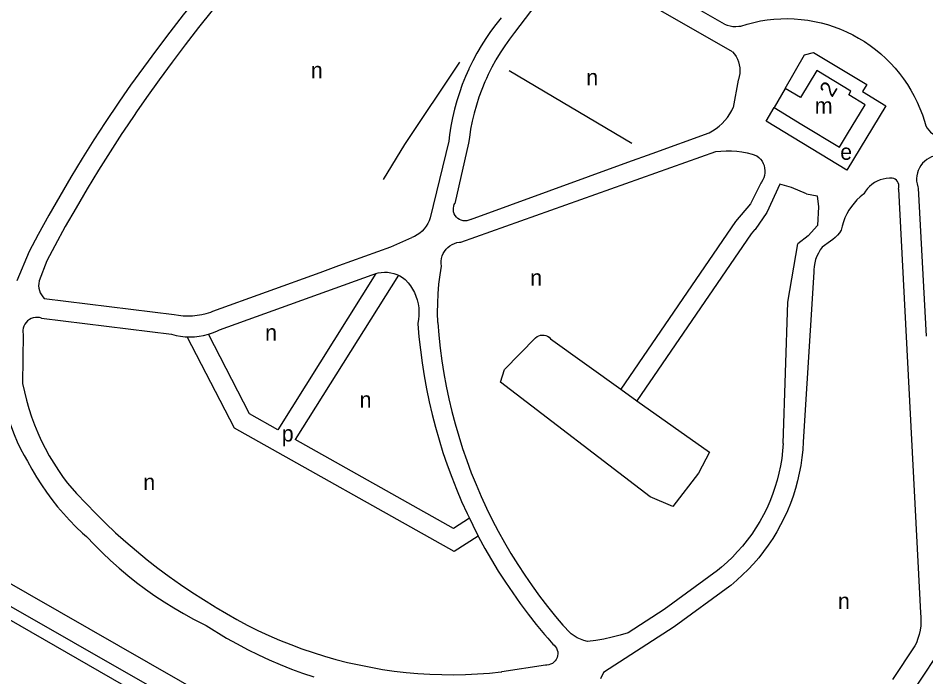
# Model space of a CAD drawing. Extents: x 157155 to 159285, y 385001 to 386651.
# Drawn here: x 158780.5 to 159008.3, y 385150.6 to 385315.8 of the extents above; entities that cross this region are included whole.
import ezdxf

# ---------------------------------------------------------------- set-up
doc = ezdxf.new("R2010")
doc.units = 0
for name, color, linetype in [('BLT_Basislijn', 7, 'Continuous'), ('BLT_Bebouwing', 7, 'Continuous'), ('BLT_Centroide', 7, 'Continuous'), ('BLT_Huisnummer', 7, 'Continuous')]:
    doc.layers.add(name, color=color, linetype=linetype)

msp = doc.modelspace()

# ---------------------------------------------------------------- linework, layer by layer
at = {"layer": 'BLT_Basislijn'}
for p, q in [((158957.77, 385314.36), (158928.1, 385331.36)), ((158917.02, 385328.1), (158905.11, 385312.23)), ((158959.82, 385307.43), (158921.7, 385329.26)), ((158523.9, 385310.24), (158946.21, 385068.98)), ((158903.73, 385302.73), (158934.55, 385284.5)), ((158961.21, 385300.27), (158959.97, 385293.43)), ((158939.64, 385281.89), (158953.93, 385287.09)), ((158888.59, 385285), (158883.93, 385265.77)), ((158893.56, 385284.46), (158890.09, 385269.37)), ((158891.6, 385259.68), (158955.6, 385282.37)), ((158933.5, 385279.72), (158939.64, 385281.89)), ((158894.04, 385265.33), (158933.5, 385279.72)), ((158966.88, 385274.47), (158964.36, 385269.26)), ((159001.44, 385272.94), (159007.03, 385166.63)), ((159006.43, 385273.2), (159008.38, 385236.11)), ((158874.07, 385258.48), (158879.27, 385260.79)), ((158984.41, 385259.91), (158982.32, 385258.42)), ((158783.22, 385257.3), (158780.15, 385249.92)), ((158860.99, 385253.76), (158874.07, 385258.48)), ((158787.65, 385254.97), (158785.75, 385249.92)), ((158856.3, 385252.06), (158860.99, 385253.76)), ((158829.33, 385242.32), (158856.3, 385252.06)), ((158831.02, 385237.62), (158869.33, 385251.46)), ((158870.3, 385251.8), (158845.69, 385212.61)), ((158875.93, 385251.36), (158850.05, 385210.15)), ((158980.24, 385252.09), (158977.56, 385209.54)), ((158786.99, 385245.56), (158819.61, 385241.52)), ((158662.43, 385240.32), (158951.28, 385075.3)), ((158786.37, 385240.59), (158818.99, 385236.55)), ((158781.71, 385236.55), (158781.59, 385224.19)), ((158914.15, 385235.44), (158931.77, 385222.79)), ((158931.77, 385222.79), (158935.82, 385219.86)), ((158917.2, 385163.58), (158919.04, 385161.63)), ((158913.42, 385160.31), (158914.68, 385158.83)), ((159005.6, 385158.37), (159000, 385149.93)), ((159010.88, 385155.73), (158959.48, 385078.25)), ((158912.82, 385153.55), (158901.91, 385151.87))]:
    msp.add_line(p, q, dxfattribs=at)
for points in [[(158828.89, 385325.2), (158825.37, 385320.96), (158821.91, 385316.67), (158818.52, 385312.33), (158815.18, 385307.94), (158811.92, 385303.5), (158808.71, 385299.02), (158807.03, 385296.58)], [(158832.71, 385321.98), (158829.21, 385317.77), (158825.78, 385313.5), (158822.41, 385309.19), (158819.1, 385304.83), (158815.86, 385300.42), (158812.68, 385295.97), (158810.18, 385292.34)], [(158522.97, 385314.23), (158948.8, 385070.96), (158946.21, 385068.98)], [(158901.7, 385315.97), (158900.35, 385314.27), (158899.07, 385312.53), (158897.85, 385310.74), (158896.69, 385308.91), (158895.87, 385307.5)], [(158957.77, 385314.36), (158958.46, 385314.09), (158959.18, 385313.9), (158959.92, 385313.79), (158960.66, 385313.76), (158961.4, 385313.81), (158961.88, 385313.88)], [(158961.88, 385313.88), (158963.51, 385314.38), (158965.16, 385314.8), (158966.83, 385315.15), (158968.51, 385315.42), (158970.2, 385315.6), (158971.9, 385315.71), (158973.6, 385315.73), (158975.3, 385315.68), (158977, 385315.55), (158978.69, 385315.33), (158980.37, 385315.04), (158982.03, 385314.67), (158983.67, 385314.22), (158985.29, 385313.7), (158986.88, 385313.1), (158988.45, 385312.42), (158989.98, 385311.68), (158991.47, 385310.86), (158992.92, 385309.97), (158994.33, 385309.02), (158995.7, 385308), (158997.01, 385306.91), (158998.27, 385305.77), (158999.48, 385304.57), (159000.63, 385303.31), (159001.71, 385302), (159002.74, 385300.64), (159003.7, 385299.24), (159004.6, 385297.79), (159005.42, 385296.3), (159006.17, 385294.77), (159006.85, 385293.21), (159007.46, 385291.62), (159007.99, 385290.01), (159008.3, 385288.81)], [(158905.11, 385312.23), (158903.84, 385310.59), (158902.63, 385308.91), (158901.5, 385307.18), (158900.43, 385305.41), (158900.31, 385305.19)], [(158895.87, 385307.5), (158895.6, 385307.04), (158894.59, 385305.13), (158893.64, 385303.18), (158893.59, 385303.05)], [(158959.82, 385307.43), (158960.29, 385306.86), (158960.7, 385306.24), (158961.04, 385305.57), (158961.31, 385304.88), (158961.51, 385304.16), (158961.62, 385303.42), (158961.66, 385302.68), (158961.61, 385301.93), (158961.49, 385301.2), (158961.29, 385300.48), (158961.21, 385300.27)], [(158973.05, 385298.22), (158977.91, 385306.62), (158980.13, 385307.25), (158993.5, 385299.22), (158992.43, 385297.45), (158998.32, 385293.88), (158988.52, 385277.69), (158968.22, 385289.99), (158970.25, 385293.44)], [(158872.21, 385275.35), (158877.55, 385284.12), (158891.34, 385304.78)], [(158900.31, 385305.19), (158899.42, 385303.59), (158898.49, 385301.74), (158898.03, 385300.73)], [(158893.59, 385303.05), (158892.77, 385301.2), (158891.97, 385299.18), (158891.25, 385297.14), (158890.6, 385295.08), (158890.03, 385292.99), (158889.54, 385290.88), (158889.12, 385288.75), (158888.79, 385286.61), (158888.59, 385285)], [(158898.03, 385300.73), (158897.64, 385299.86), (158896.85, 385297.94), (158896.14, 385296), (158895.51, 385294.03), (158894.95, 385292.03), (158894.47, 385290.02), (158894.07, 385287.98), (158893.74, 385285.94), (158893.56, 385284.46)], [(158807.03, 385296.58), (158805.58, 385294.49), (158802.51, 385289.92), (158802.36, 385289.68)], [(158953.93, 385287.09), (158954.82, 385287.58), (158955.67, 385288.13), (158956.47, 385288.76), (158957.22, 385289.44), (158957.91, 385290.18), (158958.55, 385290.97), (158959.12, 385291.81), (158959.62, 385292.7), (158959.97, 385293.43)], [(158810.18, 385292.34), (158809.57, 385291.47), (158806.92, 385287.52)], [(158802.36, 385289.68), (158799.51, 385285.3), (158796.57, 385280.64), (158793.7, 385275.93), (158790.9, 385271.19), (158788.17, 385266.4), (158785.51, 385261.58), (158783.22, 385257.3)], [(159008.3, 385288.81), (159008.65, 385288.24), (159009.06, 385287.73), (159009.53, 385287.26), (159010.06, 385286.86), (159010.62, 385286.52), (159011.23, 385286.25), (159011.86, 385286.06), (159012.52, 385285.94), (159012.83, 385285.92)], [(158806.92, 385287.52), (158806.52, 385286.92), (158803.54, 385282.33), (158800.63, 385277.7), (158797.78, 385273.02), (158795.01, 385268.3), (158792.3, 385263.55), (158789.66, 385258.75), (158787.65, 385254.97)], [(158955.6, 385282.37), (158956.91, 385282.52), (158958.23, 385282.58), (158959.55, 385282.56), (158960.87, 385282.47), (158962.18, 385282.29), (158963.47, 385282.03), (158964.75, 385281.7), (158965.95, 385281.31)], [(158965.95, 385281.31), (158966.43, 385280.92), (158966.85, 385280.47), (158967.21, 385279.97), (158967.5, 385279.43), (158967.72, 385278.86), (158967.87, 385278.26), (158967.93, 385277.64), (158967.92, 385277.03), (158967.82, 385276.42), (158967.65, 385275.83), (158967.4, 385275.27), (158967.08, 385274.74), (158966.88, 385274.47)], [(159013.18, 385281.39), (159012.49, 385281.48), (159011.79, 385281.49), (159011.1, 385281.42), (159010.42, 385281.27), (159009.76, 385281.04), (159009.14, 385280.74), (159008.55, 385280.37), (159008, 385279.93), (159007.52, 385279.44), (159007.09, 385278.89), (159006.72, 385278.3), (159006.43, 385277.67), (159006.21, 385277.01), (159006.07, 385276.32), (159006.01, 385275.63), (159006.02, 385274.93), (159006.12, 385274.25), (159006.3, 385273.57), (159006.43, 385273.2)], [(158999.2, 385275.72), (158998.41, 385275.65), (158997.64, 385275.5), (158996.89, 385275.28), (158996.16, 385274.98), (158995.47, 385274.6), (158994.81, 385274.16), (158994.21, 385273.66), (158993.66, 385273.1), (158993.17, 385272.48), (158992.75, 385271.82), (158992.67, 385271.67)], [(159001.44, 385272.94), (159001.55, 385273.33), (159001.59, 385273.73), (159001.55, 385274.13), (159001.43, 385274.51), (159001.24, 385274.86), (159000.98, 385275.17), (159000.67, 385275.42), (159000.31, 385275.61), (158999.92, 385275.72), (158999.52, 385275.75), (158999.2, 385275.72)], [(158978.36, 385271.81), (158974.59, 385273.36), (158971.7, 385274.24), (158968.44, 385267.06), (158965.52, 385262.81), (158965.35, 385262.73)], [(158978.36, 385271.81), (158981.09, 385271.29), (158981.42, 385268.52), (158981.1, 385263.85), (158978.83, 385261.27), (158976.2, 385259.24)], [(158992.67, 385271.67), (158991.83, 385270.99), (158991.04, 385270.24), (158990.31, 385269.43), (158989.64, 385268.58), (158989.03, 385267.67), (158988.49, 385266.73), (158988.03, 385265.75), (158987.63, 385264.73), (158987.31, 385263.69), (158987.08, 385262.66)], [(158894.04, 385265.33), (158893.6, 385265.14), (158893.12, 385265.02), (158892.64, 385264.99), (158892.15, 385265.03), (158891.69, 385265.16), (158891.24, 385265.36), (158890.84, 385265.62), (158890.48, 385265.96), (158890.19, 385266.34), (158889.96, 385266.77), (158889.8, 385267.23), (158889.73, 385267.71), (158889.73, 385268.19), (158889.81, 385268.67), (158889.97, 385269.13), (158890.09, 385269.37)], [(158964.36, 385269.26), (158960.55, 385264.8), (158931.77, 385222.79)], [(158883.93, 385265.77), (158883.65, 385265.03), (158883.31, 385264.32), (158882.9, 385263.65), (158882.42, 385263.02), (158881.88, 385262.45), (158881.28, 385261.93), (158880.63, 385261.48), (158879.95, 385261.09), (158879.27, 385260.79)], [(158965.35, 385262.73), (158964.52, 385261.76), (158935.82, 385219.86)], [(158987.08, 385262.66), (158986.65, 385261.99), (158986.15, 385261.38), (158985.59, 385260.81), (158984.98, 385260.3), (158984.41, 385259.91)], [(158886.72, 385253.64), (158886.66, 385254.29), (158886.68, 385254.93), (158886.77, 385255.57), (158886.95, 385256.19), (158887.2, 385256.79), (158887.52, 385257.35), (158887.9, 385257.86), (158888.35, 385258.33), (158888.86, 385258.73), (158889.41, 385259.07), (158889.99, 385259.34), (158890.61, 385259.53), (158891.24, 385259.65), (158891.6, 385259.68)], [(158972.54, 385209.14), (158973.72, 385244.63), (158976.2, 385259.24)], [(158982.32, 385258.42), (158981.81, 385257.7), (158981.36, 385256.93), (158980.99, 385256.13), (158980.68, 385255.3), (158980.46, 385254.44), (158980.31, 385253.56), (158980.24, 385252.68), (158980.24, 385252.09)], [(158885.8, 385239.52), (158885.76, 385241.92), (158885.8, 385244.31), (158885.92, 385246.7), (158886.12, 385249.08), (158886.4, 385251.46), (158886.72, 385253.64)], [(158869.33, 385251.46), (158870.07, 385251.74), (158870.3, 385251.8)], [(158870.3, 385251.8), (158870.84, 385251.95), (158871.63, 385252.08), (158872.43, 385252.13), (158873.22, 385252.1), (158874.01, 385251.99), (158874.79, 385251.81), (158875.54, 385251.55), (158875.93, 385251.36)], [(158875.93, 385251.36), (158876.27, 385251.21), (158876.95, 385250.8), (158877.59, 385250.33), (158877.71, 385250.23)], [(158877.71, 385250.23), (158878.37, 385249.49), (158878.96, 385248.7), (158879.48, 385247.87), (158879.94, 385246.99), (158880.32, 385246.09), (158880.63, 385245.15), (158880.87, 385244.2), (158881.02, 385243.22), (158881.1, 385242.24), (158881.09, 385241.26), (158881.01, 385240.28), (158880.84, 385239.3), (158880.81, 385239.17)], [(158785.75, 385249.92), (158785.64, 385249.32), (158785.62, 385248.71), (158785.67, 385248.11), (158785.81, 385247.52), (158786.02, 385246.95), (158786.3, 385246.42), (158786.65, 385245.92), (158786.99, 385245.56)], [(158819.61, 385241.52), (158820.76, 385241.31), (158821.92, 385241.19), (158823.08, 385241.15), (158824.25, 385241.18), (158825.41, 385241.3), (158826.56, 385241.5), (158827.69, 385241.77), (158828.81, 385242.12), (158829.33, 385242.32)], [(158786.37, 385240.59), (158785.85, 385240.73), (158785.32, 385240.78), (158784.79, 385240.76), (158784.26, 385240.65), (158783.76, 385240.47), (158783.29, 385240.22), (158782.86, 385239.89), (158782.49, 385239.51), (158782.18, 385239.08), (158781.93, 385238.6), (158781.76, 385238.1), (158781.67, 385237.57), (158781.65, 385237.04), (158781.71, 385236.55)], [(158880.81, 385239.17), (158881.09, 385235.88), (158881.44, 385232.61), (158881.88, 385229.35), (158882.39, 385226.09), (158882.99, 385222.86), (158883.66, 385219.63), (158884.41, 385216.43), (158885.24, 385213.24), (158886.14, 385210.07), (158887.12, 385206.93), (158888.18, 385203.81), (158889.31, 385200.72), (158890.52, 385197.66), (158891.8, 385194.62), (158893.16, 385191.62), (158893.74, 385190.4)], [(158885.8, 385239.52), (158886.07, 385236.3), (158886.42, 385233.09), (158886.85, 385229.89), (158887.36, 385226.7), (158887.95, 385223.52), (158888.62, 385220.36), (158889.36, 385217.21), (158890.19, 385214.09), (158891.09, 385210.99), (158892.06, 385207.91), (158893.12, 385204.85), (158894.24, 385201.82), (158895.45, 385198.82), (158896.72, 385195.85), (158898.07, 385192.92), (158899.49, 385190.01), (158900.99, 385187.15), (158902.55, 385184.32), (158904.18, 385181.53), (158905.89, 385178.78), (158907.65, 385176.08), (158909.49, 385173.42), (158911.39, 385170.81), (158913.36, 385168.24), (158915.38, 385165.73), (158917.2, 385163.58)], [(158818.99, 385236.55), (158820.12, 385236.27), (158821.26, 385236.07), (158822.41, 385235.94), (158822.93, 385235.92)], [(158822.93, 385235.92), (158823.57, 385235.9), (158824.72, 385235.93), (158825.88, 385236.05), (158827.02, 385236.24), (158828.24, 385236.55)], [(158828.24, 385236.55), (158829.25, 385236.87), (158830.33, 385237.29), (158831.02, 385237.62)], [(158845.69, 385212.61), (158838.58, 385216.6), (158828.24, 385236.55)], [(158910.38, 385235.67), (158910.75, 385235.95), (158911.15, 385236.16), (158911.59, 385236.29), (158912.05, 385236.35), (158912.5, 385236.33), (158912.95, 385236.23), (158913.38, 385236.06), (158913.76, 385235.81), (158914.15, 385235.44)], [(158895.99, 385185.9), (158889.91, 385182.03), (158834.82, 385212.97), (158822.93, 385235.92)], [(158935.82, 385219.86), (158953.99, 385206.97), (158951.23, 385201.72), (158944.81, 385193.32), (158939.11, 385195.79), (158901.59, 385224.53), (158902.56, 385227.68), (158910.38, 385235.67)], [(158781.59, 385224.19), (158782.03, 385222.08), (158782.55, 385219.98), (158783.15, 385217.91), (158783.82, 385215.86), (158784.57, 385213.83), (158785.39, 385211.83), (158786.28, 385209.87), (158787.25, 385207.94), (158788.29, 385206.05), (158789.4, 385204.19), (158790.57, 385202.38), (158791.81, 385200.61), (158792.87, 385199.22)], [(158776.73, 385220.7), (158777.12, 385218.79), (158777.59, 385216.9), (158778.14, 385215.04), (158778.77, 385213.2), (158779.46, 385211.38), (158780.24, 385209.59), (158781.09, 385207.84), (158782, 385206.13), (158782.85, 385204.68)], [(158893.74, 385190.4), (158889.75, 385187.86), (158850.05, 385210.15)], [(158972.54, 385209.14), (158972.39, 385207.27), (158972.16, 385205.41), (158971.85, 385203.56), (158971.47, 385201.73), (158971, 385199.91), (158970.46, 385198.11), (158969.85, 385196.34), (158969.15, 385194.6), (158968.39, 385192.88), (158967.55, 385191.21), (158966.64, 385189.57), (158965.66, 385187.96), (158964.62, 385186.41), (158963.51, 385184.9), (158962.33, 385183.43), (158961.1, 385182.02), (158959.8, 385180.66), (158958.45, 385179.36), (158957.05, 385178.12), (158956.01, 385177.27)], [(158977.56, 385209.54), (158977.44, 385207.57), (158977.23, 385205.6), (158976.95, 385203.64), (158976.58, 385201.7), (158976.14, 385199.77), (158975.62, 385197.86), (158975.02, 385195.97), (158974.35, 385194.11), (158973.6, 385192.28), (158972.78, 385190.47), (158971.88, 385188.71), (158970.92, 385186.98), (158969.89, 385185.29), (158968.79, 385183.64), (158967.62, 385182.04), (158966.39, 385180.49), (158965.1, 385178.99), (158963.75, 385177.55), (158962.34, 385176.16), (158960.88, 385174.82), (158959.36, 385173.55), (158959.12, 385173.35)], [(158782.85, 385204.68), (158783.93, 385202.68), (158785.09, 385200.71), (158786.31, 385198.79), (158787.6, 385196.91), (158788.95, 385195.08), (158790.37, 385193.29), (158791.85, 385191.56), (158793.39, 385189.88), (158794.99, 385188.26), (158796.64, 385186.69), (158797.65, 385185.79)], [(158792.87, 385199.22), (158795.16, 385196.62), (158797.52, 385194.07), (158799.94, 385191.58), (158802.41, 385189.15), (158804.94, 385186.77), (158807.52, 385184.46), (158810.15, 385182.2), (158812.84, 385180), (158815.58, 385177.87), (158818.36, 385175.8), (158821.19, 385173.79), (158824.07, 385171.85), (158826.99, 385169.98), (158829.95, 385168.18), (158830.2, 385168.03)], [(158893.74, 385190.4), (158894.58, 385188.65), (158895.99, 385185.9)], [(158797.65, 385185.79), (158799.6, 385183.73), (158801.61, 385181.72), (158803.68, 385179.78), (158805.8, 385177.89), (158807.98, 385176.07), (158810.2, 385174.3), (158812.48, 385172.6), (158814.8, 385170.96), (158817.16, 385169.39), (158819.57, 385167.89), (158822.02, 385166.46), (158824.51, 385165.09), (158827.7, 385163.48)], [(158895.99, 385185.9), (158896.08, 385185.72), (158897.65, 385182.83), (158899.29, 385179.97), (158901, 385177.16), (158902.78, 385174.38), (158904.62, 385171.66), (158906.53, 385168.97), (158908.5, 385166.34), (158910.54, 385163.75), (158912.64, 385161.21), (158913.42, 385160.31)], [(158956.01, 385177.27), (158942.65, 385167.54), (158933.64, 385161.63)], [(158959.12, 385173.35), (158945.13, 385163.18), (158927.42, 385151.68), (158926.66, 385150.07)], [(158830.2, 385168.03), (158832.76, 385166.48), (158835.36, 385165.01), (158837.99, 385163.6), (158840.67, 385162.26), (158843.38, 385161), (158846.12, 385159.81), (158848.89, 385158.69), (158851.69, 385157.65), (158854.52, 385156.68), (158857.37, 385155.79), (158860.25, 385154.98), (158863.15, 385154.24), (158866.06, 385153.58), (158868.99, 385153), (158871.94, 385152.49), (158874.9, 385152.07), (158877.87, 385151.73), (158880.84, 385151.46), (158883.83, 385151.28), (158886.81, 385151.17), (158889.8, 385151.15), (158892.79, 385151.2), (158895.78, 385151.34), (158898.76, 385151.55), (158901.73, 385151.85), (158901.91, 385151.87)], [(159007.03, 385166.63), (159007.12, 385165.55), (159007.12, 385164.46), (159007.05, 385163.38), (159006.9, 385162.3), (159006.67, 385161.24), (159006.36, 385160.2), (159005.98, 385159.18), (159005.6, 385158.37)], [(158827.7, 385163.48), (158832.81, 385160.33), (158835.43, 385158.86), (158838.09, 385157.45), (158840.78, 385156.12), (158843.51, 385154.86), (158846.27, 385153.68), (158849.06, 385152.57), (158851.88, 385151.53), (158854.73, 385150.57)], [(158923.39, 385159.46), (158922.51, 385159.7), (158921.65, 385160.02), (158920.83, 385160.41), (158920.05, 385160.88), (158919.31, 385161.41), (158919.04, 385161.63)], [(158933.64, 385161.63), (158931.62, 385161.04), (158929.59, 385160.53), (158927.54, 385160.09), (158925.47, 385159.73), (158923.39, 385159.46)], [(158914.68, 385158.83), (158915.06, 385158.53), (158915.38, 385158.17), (158915.63, 385157.76), (158915.82, 385157.32), (158915.93, 385156.85), (158915.96, 385156.37), (158915.9, 385155.89), (158915.77, 385155.43), (158915.57, 385154.99), (158915.3, 385154.6), (158914.96, 385154.25), (158914.58, 385153.97), (158914.15, 385153.75), (158913.69, 385153.61), (158913.21, 385153.54), (158912.82, 385153.55)]]:
    msp.add_lwpolyline(points, dxfattribs=at)
at = {"layer": 'BLT_Bebouwing'}
for p, q in [((158973.05, 385298.22), (158970.25, 385293.44)), ((158976.86, 385295.91), (158973.05, 385298.22)), ((158986.64, 385283.51), (158988.64, 385286.81))]:
    msp.add_line(p, q, dxfattribs=at)
for points in [[(158988.64, 385286.81), (158993.07, 385294.12), (158988.97, 385296.6), (158989.54, 385297.54), (158980.99, 385302.72), (158976.86, 385295.91)], [(158970.25, 385293.44), (158977.23, 385289.21), (158986.64, 385283.51)]]:
    msp.add_lwpolyline(points, dxfattribs=at)

# ---------------------------------------------------------------- texts
at = {"layer": 'BLT_Centroide'}
for s, p in [('n', (158853.95, 385300.79)), ('n', (158923.09, 385299.01)), ('m', (158980.47, 385291.91)), ('e', (158986.85, 385280.32)), ('n', (158909.03, 385248.76)), ('n', (158842.48, 385234.98)), ('n', (158866.19, 385218.15)), ('p', (158846.66, 385209.65)), ('n', (158811.88, 385197.48)), ('n', (158986.28, 385167.64))]:
    msp.add_text(s, height=4, dxfattribs=at).set_placement(p)
at = {"layer": 'BLT_Huisnummer'}
msp.add_text('2', height=4, rotation=58.7948, dxfattribs=at).set_placement((158984.8, 385295.79))

doc.saveas('drawing.dxf')
